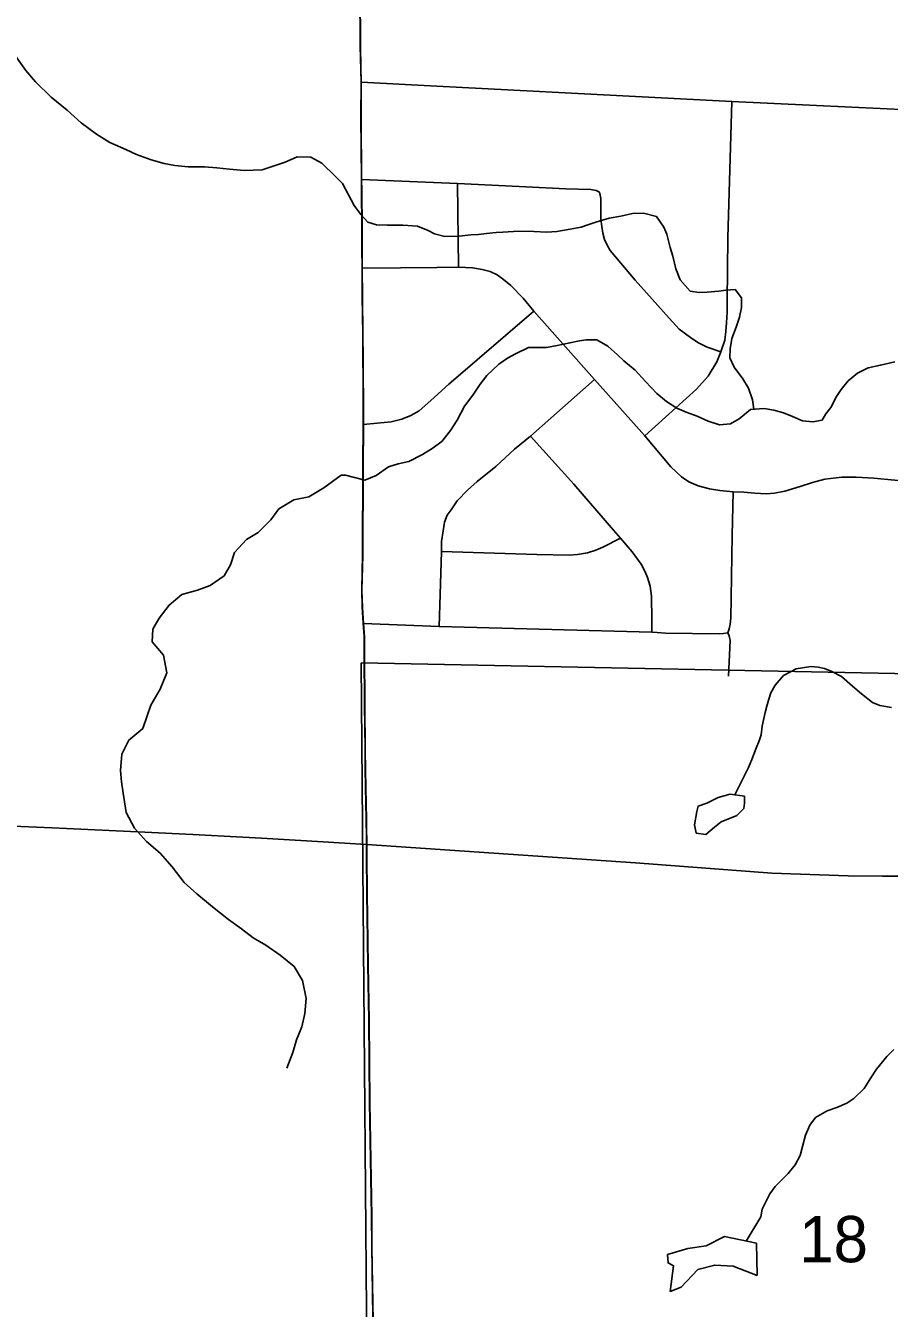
# Model space of a CAD drawing. Extents: x 0 to 34, y -5 to 22.
# Drawn here: x 5.836 to 6.617, y 14.888 to 16.047 of the extents above; entities that cross this region are included whole.
import ezdxf

# ---------------------------------------------------------------- set-up
doc = ezdxf.new("R2010")
doc.units = 0
for name, color, linetype in [('GM_X_County_Road', 7, 'Continuous'), ('GM_X_Minor_Lake', 7, 'Continuous'), ('GM_X_Minor_River', 7, 'Continuous'), ('GM_X_Section', 7, 'Continuous'), ('GM_X_Section_Text', 7, 'Continuous'), ('GM_X_Township_Road', 7, 'Continuous'), ('GM_X_US_Route', 7, 'Continuous'), ('SC_Scratch2', 7, 'Continuous'), ('SH_Cut_Line', 7, 'Continuous')]:
    doc.layers.add(name, color=color, linetype=linetype)

msp = doc.modelspace()

# ---------------------------------------------------------------- linework, layer by layer
at = {"layer": 'GM_X_County_Road'}
msp.add_lwpolyline([(6.1391, 15.9958), (6.2017, 15.9925), (6.4743, 15.9785), (6.653, 15.9701), (6.6892, 15.9687), (6.7675, 15.9642), (6.9301, 15.9567), (6.9889, 15.9539)], dxfattribs=at)
at = {"layer": 'GM_X_Minor_Lake'}
for points in [[(6.4729, 15.3523), (6.4619, 15.3492), (6.4517, 15.3441), (6.4438, 15.3414), (6.4427, 15.3368), (6.4405, 15.3247), (6.4421, 15.3171), (6.4508, 15.316), (6.4587, 15.3225), (6.4648, 15.3272), (6.4787, 15.333), (6.4851, 15.3395), (6.4858, 15.3441), (6.4858, 15.3505)], [(6.4858, 15.3505), (6.4729, 15.3523)], [(6.4965, 14.9464), (6.4676, 14.9526), (6.451, 14.9441), (6.4344, 14.9417), (6.4162, 14.9362), (6.4167, 14.9286), (6.4216, 14.926), (6.4184, 14.9028), (6.4286, 14.9067), (6.4436, 14.9228), (6.4588, 14.9267), (6.4755, 14.9257), (6.4971, 14.9172)], [(6.4971, 14.9172), (6.4965, 14.9464)]]:
    msp.add_lwpolyline(points, dxfattribs=at)
at = {"layer": 'GM_X_Minor_River'}
for points in [[(6.122, 15.9042), (6.1156, 15.9111), (6.1034, 15.9227), (6.0935, 15.928), (6.081, 15.9283), (6.0704, 15.9236), (6.0496, 15.9166), (6.0333, 15.9161), (6.02, 15.9172), (6.0086, 15.9186), (5.9972, 15.9193), (5.9824, 15.9195), (5.9706, 15.9206), (5.9608, 15.9224), (5.949, 15.9257), (5.9357, 15.9306), (5.9262, 15.9351), (5.9117, 15.9414), (5.8995, 15.9489), (5.8858, 15.9591), (5.8732, 15.9707), (5.8587, 15.9824), (5.8445, 15.9963), (5.8357, 16.0065), (5.8262, 16.0201)], [(6.4943, 15.7003), (6.4929, 15.7088), (6.4894, 15.7194), (6.4844, 15.7277), (6.4764, 15.7383), (6.4725, 15.7466), (6.4728, 15.755), (6.4742, 15.7641), (6.4783, 15.7744), (6.4813, 15.7836), (6.4831, 15.7923), (6.483, 15.801), (6.4773, 15.8086), (6.4689, 15.8078), (6.4625, 15.8069), (6.4519, 15.8061), (6.4447, 15.8057), (6.4367, 15.8071), (6.4275, 15.8173), (6.4236, 15.8271), (6.4209, 15.8385), (6.4185, 15.8465), (6.4154, 15.8586), (6.4127, 15.865), (6.4062, 15.8745), (6.3944, 15.8774), (6.3845, 15.8773), (6.3739, 15.8749), (6.3633, 15.8729), (6.3512, 15.8694), (6.344, 15.8671), (6.338, 15.8648), (6.3282, 15.8631), (6.316, 15.8608), (6.3069, 15.8603), (6.2952, 15.861), (6.2815, 15.8612), (6.2671, 15.8603), (6.2611, 15.8599), (6.2524, 15.8591), (6.2452, 15.8583), (6.2383, 15.8578), (6.2277, 15.8566), (6.2148, 15.8565), (6.2053, 15.8587), (6.1996, 15.862), (6.1901, 15.8658), (6.1768, 15.8668), (6.1628, 15.8667), (6.153, 15.867), (6.145, 15.8695), (6.1388, 15.8763), (6.1327, 15.8843), (6.122, 15.9042)], [(6.1248, 15.6407), (6.1424, 15.6363), (6.1526, 15.6405), (6.1636, 15.6482), (6.1726, 15.651), (6.1821, 15.6529), (6.1946, 15.6595), (6.2032, 15.6649), (6.2119, 15.6711), (6.2198, 15.681), (6.2258, 15.6905), (6.2291, 15.6967), (6.2325, 15.7031), (6.24, 15.7131), (6.2467, 15.723), (6.2527, 15.7307), (6.2636, 15.741), (6.2715, 15.7464), (6.2787, 15.7503), (6.2904, 15.7561), (6.3067, 15.7562), (6.3162, 15.7578), (6.3279, 15.7602), (6.3366, 15.7622), (6.3427, 15.763), (6.3522, 15.7631), (6.3621, 15.7574), (6.3708, 15.7495), (6.3766, 15.7439), (6.3869, 15.7356), (6.3961, 15.7255), (6.4064, 15.7145), (6.4152, 15.7074), (6.4247, 15.7014), (6.4331, 15.6977), (6.443, 15.6939), (6.4529, 15.6895), (6.4632, 15.6861), (6.473, 15.687), (6.4809, 15.6916), (6.4911, 15.7001), (6.5036, 15.7009), (6.5123, 15.6995), (6.5211, 15.6969), (6.5291, 15.6936), (6.5382, 15.6898), (6.5477, 15.6888), (6.556, 15.6904), (6.5594, 15.6961), (6.5639, 15.7018), (6.5691, 15.7118), (6.5732, 15.7182), (6.5796, 15.7259), (6.5879, 15.7328), (6.5977, 15.7378), (6.6087, 15.7402), (6.6219, 15.743)], [(6.1248, 15.6407), (6.121, 15.6407), (6.1052, 15.6291), (6.0916, 15.6211), (6.078, 15.6183), (6.0644, 15.6102), (6.0572, 15.6003), (6.0459, 15.5888), (6.0354, 15.5826), (6.0244, 15.5708), (6.0207, 15.5597), (6.0151, 15.5498), (6.0023, 15.541), (5.9909, 15.5367), (5.9769, 15.5328), (5.9653, 15.5232), (5.9562, 15.5114), (5.9506, 15.5015), (5.9499, 15.4901), (5.9603, 15.478), (5.9631, 15.462), (5.9571, 15.4472), (5.9489, 15.4327), (5.9455, 15.4232), (5.9414, 15.4117), (5.929, 15.401), (5.9226, 15.3884), (5.9212, 15.3736), (5.9221, 15.3634), (5.9237, 15.3531), (5.9264, 15.3357), (5.9341, 15.3217), (5.9448, 15.3096), (5.9571, 15.299), (5.9681, 15.2866), (5.9789, 15.2726), (5.9903, 15.2621), (6.0044, 15.2504), (6.0189, 15.2391), (6.0308, 15.2305), (6.0414, 15.2226), (6.0529, 15.2158), (6.0658, 15.2068), (6.0784, 15.1967), (6.0861, 15.1838), (6.0893, 15.1675), (6.0882, 15.1542), (6.0853, 15.142), (6.0804, 15.1302), (6.0771, 15.1188), (6.0719, 15.1047)], [(6.4771, 15.3517), (6.4894, 15.3764), (6.4923, 15.3836), (6.4964, 15.3939), (6.499, 15.4004), (6.5009, 15.4061), (6.5019, 15.4137), (6.5034, 15.4206), (6.5045, 15.4263), (6.5059, 15.432), (6.5078, 15.4381), (6.5096, 15.4438), (6.5134, 15.451), (6.5212, 15.4595), (6.5326, 15.4656), (6.5458, 15.4677), (6.5523, 15.467), (6.558, 15.4659), (6.5648, 15.4633), (6.5736, 15.4588), (6.5835, 15.4501), (6.5915, 15.443), (6.6015, 15.4351), (6.6083, 15.4325), (6.6186, 15.4307)], [(6.4872, 14.9484), (6.5005, 14.9704), (6.5019, 14.9772), (6.5086, 14.991), (6.5135, 14.9978), (6.5252, 15.0093), (6.5315, 15.0174), (6.536, 15.0258), (6.5382, 15.0338), (6.5408, 15.044), (6.5449, 15.0532), (6.5501, 15.0601), (6.5607, 15.0662), (6.5694, 15.069), (6.5784, 15.0729), (6.5848, 15.0771), (6.5939, 15.0863), (6.5999, 15.0958), (6.6051, 15.1039), (6.6145, 15.1153), (6.6209, 15.1215)]]:
    msp.add_lwpolyline(points, dxfattribs=at)
at = {"layer": 'GM_X_Section'}
msp.add_lwpolyline([(6.139, 15.4711), (6.9989, 15.4538), (6.9822, 14.4457), (6.1471, 14.4654), (6.1461, 14.6292)], close=True, dxfattribs=at)
at = {"layer": 'GM_X_Township_Road'}
for p, q in [((6.1391, 15.9958), (6.1388, 16.0099)), ((6.2271, 15.8287), (6.2263, 15.9042)), ((6.4747, 15.5861), (6.4755, 15.6256))]:
    msp.add_line(p, q, dxfattribs=at)
for points in [[(6.1388, 16.0099), (6.1384, 16.0281), (6.138, 16.0782), (6.1379, 16.0999), (6.1374, 16.1424), (6.1371, 16.1608), (6.1369, 16.1806), (6.1361, 16.2178), (6.1357, 16.2644), (6.1354, 16.3419), (6.1351, 16.3612), (6.1349, 16.3793), (6.1345, 16.4035), (6.1342, 16.429), (6.1339, 16.4688)], [(6.1394, 15.9079), (6.1389, 15.9633), (6.1391, 15.9958)], [(6.3956, 15.6763), (6.4425, 15.7183), (6.4529, 15.7303), (6.4606, 15.7431), (6.4643, 15.7521), (6.468, 15.7627), (6.4688, 15.7706), (6.4696, 15.7784), (6.4702, 15.788), (6.4702, 15.7979), (6.4706, 15.8552), (6.4743, 15.9785)], [(6.14, 15.8277), (6.1399, 15.8453), (6.1398, 15.8639), (6.1395, 15.8981), (6.1394, 15.9079)], [(6.1394, 15.9079), (6.2263, 15.9042), (6.2818, 15.9016), (6.3241, 15.8996), (6.3469, 15.8988), (6.3516, 15.898), (6.3547, 15.8964)], [(6.4643, 15.7521), (6.4519, 15.7564), (6.4435, 15.7607), (6.4368, 15.7651), (6.4266, 15.7727), (6.4176, 15.7827), (6.3869, 15.8169), (6.3643, 15.8438), (6.3616, 15.8485), (6.359, 15.8538), (6.3577, 15.8595), (6.3567, 15.8654), (6.3559, 15.8721), (6.3557, 15.8907), (6.3553, 15.8937), (6.3547, 15.8964)], [(6.14, 15.8277), (6.1745, 15.828), (6.2076, 15.8284), (6.2271, 15.8287), (6.2398, 15.8281), (6.2485, 15.8265), (6.2557, 15.8248), (6.262, 15.8217), (6.2679, 15.8177), (6.2744, 15.8122), (6.2856, 15.8006), (6.2952, 15.789), (6.3502, 15.7272), (6.3956, 15.6763), (6.4192, 15.6481), (6.4287, 15.6391), (6.4355, 15.6346), (6.4438, 15.631), (6.454, 15.6283), (6.4636, 15.6267), (6.4755, 15.6256), (6.4851, 15.6252), (6.4951, 15.6245), (6.5055, 15.6237), (6.5128, 15.6245), (6.5222, 15.6262), (6.5362, 15.6303), (6.5474, 15.6341), (6.5584, 15.6372), (6.5737, 15.639), (6.5868, 15.6388), (6.6029, 15.638), (6.6153, 15.6368), (6.6247, 15.636)], [(6.141, 15.6866), (6.1411, 15.6957), (6.1411, 15.7119), (6.1409, 15.7274), (6.1408, 15.746), (6.1406, 15.7677), (6.1401, 15.802), (6.14, 15.8277)], [(6.141, 15.6866), (6.1536, 15.6877), (6.1662, 15.6889), (6.1758, 15.6912), (6.1841, 15.6946), (6.1915, 15.6989), (6.2021, 15.7081), (6.2184, 15.723), (6.2952, 15.789)], [(6.2096, 15.5039), (6.2116, 15.5716), (6.2118, 15.5807), (6.2131, 15.5905), (6.2143, 15.5981), (6.2169, 15.6044), (6.2204, 15.6095), (6.2259, 15.6174), (6.2351, 15.627), (6.244, 15.6351), (6.2607, 15.6486), (6.2777, 15.6643), (6.2923, 15.6759), (6.3502, 15.7272)], [(6.1411, 15.5065), (6.1401, 15.5208), (6.1397, 15.5367), (6.1405, 15.5683), (6.1407, 15.6476), (6.141, 15.6866)], [(6.4019, 15.4987), (6.402, 15.51), (6.4015, 15.5312), (6.4005, 15.5404), (6.3981, 15.5481), (6.3958, 15.5534), (6.3924, 15.5602), (6.3842, 15.5714), (6.3736, 15.5838), (6.3673, 15.5909), (6.3315, 15.6325), (6.2923, 15.6759)], [(6.2116, 15.5716), (6.2978, 15.5691), (6.3272, 15.5685), (6.3347, 15.5689), (6.3437, 15.5705), (6.3512, 15.573), (6.3575, 15.5756), (6.3736, 15.5838)], [(6.4712, 15.4591), (6.4727, 15.4913), (6.472, 15.4954), (6.4708, 15.4982), (6.4718, 15.5017), (6.4727, 15.506), (6.4733, 15.5113), (6.4747, 15.5861)], [(6.144, 15.3188), (6.1438, 15.3298), (6.1435, 15.3432), (6.1432, 15.3587), (6.1429, 15.3742), (6.1427, 15.3924), (6.1422, 15.4327), (6.1421, 15.4796), (6.1419, 15.4946), (6.1411, 15.5065)], [(6.1411, 15.5065), (6.2096, 15.5039), (6.4019, 15.4987), (6.4068, 15.4984), (6.4144, 15.498), (6.4629, 15.4974), (6.4667, 15.4976), (6.4708, 15.4982)], [(5.4238, 15.3782), (5.4295, 15.3769), (5.4387, 15.3749), (5.4781, 15.3663), (5.5295, 15.3539), (5.572, 15.3444), (5.6115, 15.3363), (5.6247, 15.3339), (5.6361, 15.3324), (5.6491, 15.331), (5.6638, 15.3302), (5.7601, 15.326), (5.8594, 15.3218), (5.9432, 15.3181), (5.9867, 15.3159), (6.0488, 15.3127), (6.1047, 15.3092), (6.1388, 15.3071), (6.1441, 15.3068)], [(6.1441, 15.3068), (6.1441, 15.3117), (6.144, 15.3188)], [(6.1525, 14.6385), (6.1523, 14.6635), (6.1517, 14.6944), (6.1513, 14.7224), (6.1509, 14.744), (6.1508, 14.7565), (6.1504, 14.7906), (6.1503, 14.8098), (6.1502, 14.859), (6.1488, 14.9428), (6.1486, 14.9707), (6.1469, 15.0732), (6.1462, 15.1478), (6.1454, 15.1975), (6.1445, 15.2627), (6.1441, 15.2967), (6.1441, 15.2993), (6.1441, 15.3023), (6.1441, 15.3068)], [(6.1441, 15.3068), (6.3871, 15.2902), (6.5104, 15.281), (6.5794, 15.2786), (6.6106, 15.2782), (6.6334, 15.2782), (6.7624, 15.2739), (6.9205, 15.2682), (6.9931, 15.2665), (7.0008, 15.2663)]]:
    msp.add_lwpolyline(points, dxfattribs=at)
at = {"layer": 'GM_X_US_Route'}
for points in [[(6.1499, 14.8595), (6.1486, 14.9434), (6.1484, 14.9713), (6.1467, 15.0738), (6.146, 15.1483), (6.1452, 15.198), (6.1443, 15.2632), (6.1439, 15.2972), (6.1438, 15.2999), (6.1439, 15.3028), (6.1439, 15.3074), (6.1439, 15.3123), (6.1436, 15.3304), (6.1433, 15.3437), (6.143, 15.3592), (6.1427, 15.3748), (6.1425, 15.3929), (6.142, 15.4333), (6.1418, 15.4801), (6.1417, 15.4951), (6.1408, 15.507), (6.1399, 15.5214), (6.1395, 15.5373), (6.1403, 15.5689), (6.1405, 15.6481), (6.1408, 15.6871), (6.1409, 15.6962), (6.1409, 15.7125), (6.1407, 15.728), (6.1406, 15.7466), (6.1404, 15.7682), (6.1399, 15.8025), (6.1398, 15.8282), (6.1397, 15.8458), (6.1396, 15.8645), (6.1393, 15.8986), (6.1392, 15.9085), (6.1387, 15.9639), (6.1389, 15.9963), (6.1382, 16.0286), (6.1378, 16.0787)], [(6.1378, 16.0787), (6.1382, 16.0286), (6.1389, 15.9963), (6.1387, 15.9639), (6.1392, 15.9085), (6.1393, 15.8986), (6.1396, 15.8645), (6.1397, 15.8458), (6.1398, 15.8282), (6.1399, 15.8025), (6.1404, 15.7682), (6.1406, 15.7466), (6.1407, 15.728), (6.1409, 15.7125), (6.1409, 15.6962), (6.1408, 15.6871), (6.1405, 15.6481), (6.1403, 15.5689), (6.1395, 15.5373), (6.1399, 15.5214), (6.1408, 15.507), (6.1417, 15.4951), (6.1418, 15.4801), (6.142, 15.4333), (6.1425, 15.3929), (6.1427, 15.3748), (6.143, 15.3592), (6.1433, 15.3437), (6.1436, 15.3304), (6.1439, 15.3123), (6.1439, 15.3074), (6.1439, 15.3028), (6.1438, 15.2999), (6.1439, 15.2972), (6.1443, 15.2632), (6.1452, 15.198), (6.146, 15.1483), (6.1467, 15.0738), (6.1484, 14.9713), (6.1486, 14.9434), (6.1499, 14.8595)]]:
    msp.add_lwpolyline(points, dxfattribs=at)
at = {"layer": 'SC_Scratch2'}
msp.add_lwpolyline([(6.1378, 16.0787), (6.1382, 16.0286), (6.1389, 15.9963), (6.1387, 15.9639), (6.1392, 15.9085), (6.1393, 15.8986), (6.1396, 15.8645), (6.1397, 15.8458), (6.1398, 15.8282), (6.1399, 15.8025), (6.1404, 15.7682), (6.1406, 15.7466), (6.1407, 15.728), (6.1409, 15.7125), (6.1409, 15.6962), (6.1408, 15.6871), (6.1405, 15.6481), (6.1403, 15.5689), (6.1395, 15.5373), (6.1399, 15.5214), (6.1408, 15.507), (6.1417, 15.4951), (6.1418, 15.4801), (6.142, 15.4333), (6.1425, 15.3929), (6.1427, 15.3748), (6.143, 15.3592), (6.1433, 15.3437), (6.1436, 15.3304), (6.1439, 15.3123), (6.1439, 15.3074), (6.1439, 15.3028), (6.1438, 15.2999), (6.1439, 15.2972), (6.1443, 15.2632), (6.1452, 15.198), (6.146, 15.1483), (6.1467, 15.0738), (6.1484, 14.9713), (6.1486, 14.9434), (6.1499, 14.8595)], dxfattribs=at)
at = {"layer": 'SH_Cut_Line'}
for points in [[(6.1378, 16.0787), (6.1382, 16.0286), (6.1389, 15.9963), (6.1387, 15.9639), (6.1392, 15.9085), (6.1393, 15.8986), (6.1396, 15.8645), (6.1397, 15.8458), (6.1398, 15.8282), (6.1399, 15.8025), (6.1404, 15.7682), (6.1406, 15.7466), (6.1407, 15.728), (6.1409, 15.7125), (6.1409, 15.6962), (6.1408, 15.6871), (6.1405, 15.6481), (6.1403, 15.5689), (6.1395, 15.5373), (6.1399, 15.5214), (6.1408, 15.507), (6.1417, 15.4951), (6.1418, 15.4801), (6.142, 15.4333), (6.1425, 15.3929), (6.1427, 15.3748), (6.143, 15.3592), (6.1433, 15.3437), (6.1436, 15.3304), (6.1439, 15.3123), (6.1439, 15.3074), (6.1439, 15.3028), (6.1438, 15.2999), (6.1439, 15.2972), (6.1443, 15.2632), (6.1452, 15.198), (6.146, 15.1483), (6.1467, 15.0738), (6.1484, 14.9713), (6.1486, 14.9434), (6.1499, 14.8595)], [(6.1499, 14.8595), (6.1486, 14.9434), (6.1484, 14.9713), (6.1467, 15.0738), (6.146, 15.1483), (6.1452, 15.198), (6.1443, 15.2632), (6.1439, 15.2972), (6.1438, 15.2999), (6.1439, 15.3028), (6.1439, 15.3074), (6.1439, 15.3123), (6.1436, 15.3304), (6.1433, 15.3437), (6.143, 15.3592), (6.1427, 15.3748), (6.1425, 15.3929), (6.142, 15.4333), (6.1418, 15.4801), (6.1417, 15.4951), (6.1408, 15.507), (6.1399, 15.5214), (6.1395, 15.5373), (6.1403, 15.5689), (6.1405, 15.6481), (6.1408, 15.6871), (6.1409, 15.6962), (6.1409, 15.7125), (6.1407, 15.728), (6.1406, 15.7466), (6.1404, 15.7682), (6.1399, 15.8025), (6.1398, 15.8282), (6.1397, 15.8458), (6.1396, 15.8645), (6.1393, 15.8986), (6.1392, 15.9085), (6.1387, 15.9639), (6.1389, 15.9963), (6.1382, 16.0286), (6.1378, 16.0787)]]:
    msp.add_lwpolyline(points, dxfattribs=at)

# ---------------------------------------------------------------- texts
at = {"layer": 'GM_X_Section_Text'}
msp.add_text('18', height=0.04186, rotation=0, dxfattribs=at).set_placement((6.5352, 14.9292))

doc.saveas('drawing.dxf')
